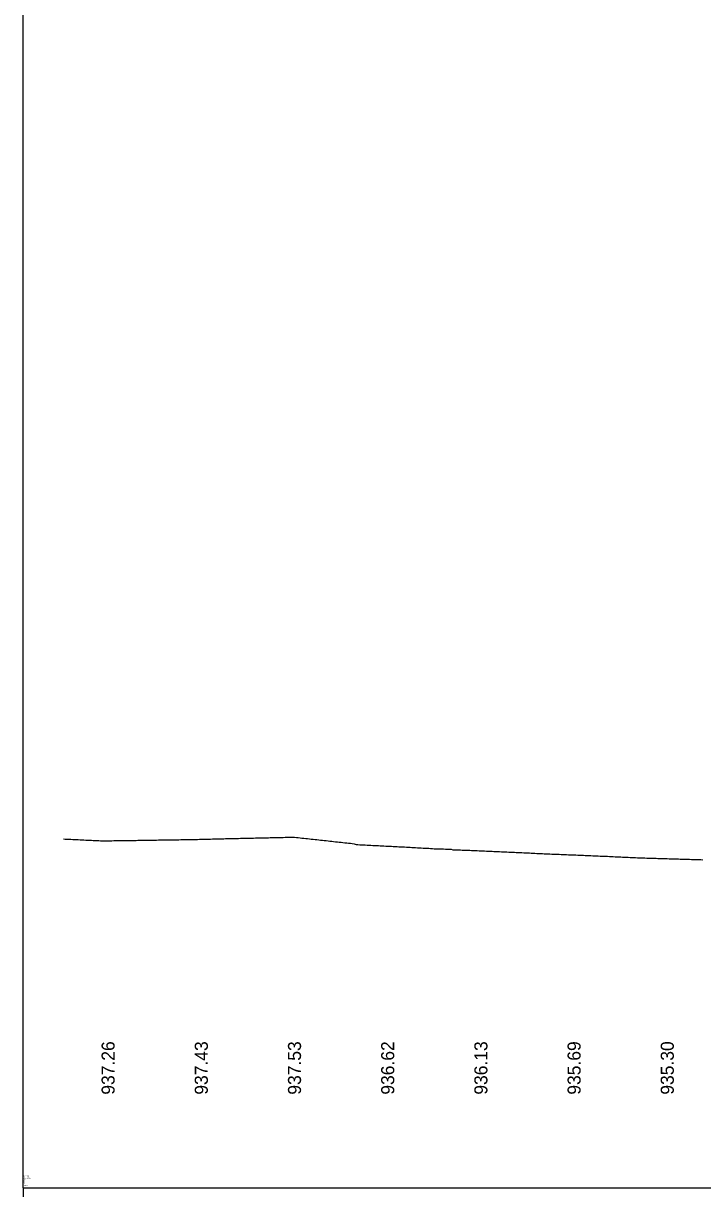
# Model space of a CAD drawing. Extents: x 1573485 to 1576468, y 1104256 to 1106756.
# Drawn here: x 1574956 to 1575320, y 1105506 to 1106131 of the extents above; entities that cross this region are included whole.
import ezdxf

# ---------------------------------------------------------------- set-up
doc = ezdxf.new("R2010")
doc.units = 0
for name, color, linetype in [('RD_DDB_Profile_EX', 7, 'Continuous'), ('RD_DDB_StripGrade', 7, 'Continuous'), ('RD_GPK_Profile_Cell', 7, 'Continuous')]:
    doc.layers.add(name, color=color, linetype=linetype)

msp = doc.modelspace()

# ---------------------------------------------------------------- linework, layer by layer
at = {"layer": 'RD_DDB_Profile_EX'}
for points in [[(1574977.5, 1105693.27), (1574978.5, 1105693.22), (1574979.5, 1105693.18), (1574980.5, 1105693.13), (1574981.5, 1105693.08), (1574982.5, 1105693.03), (1574983.5, 1105692.98), (1574984.5, 1105692.94), (1574985.5, 1105692.89), (1574986.5, 1105692.84), (1574987.5, 1105692.79), (1574988.5, 1105692.75), (1574989.5, 1105692.7), (1574990.5, 1105692.65), (1574991.5, 1105692.6), (1574992.5, 1105692.56), (1574993.5, 1105692.51), (1574994.5, 1105692.46), (1574995.5, 1105692.42), (1574996.5, 1105692.37), (1574997.5, 1105692.32), (1574998.5, 1105692.28), (1574999.5, 1105692.29), (1575000.5, 1105692.3), (1575001.5, 1105692.32), (1575002.5, 1105692.33), (1575003.5, 1105692.34), (1575004.5, 1105692.36), (1575005.5, 1105692.37), (1575006.5, 1105692.38), (1575007.5, 1105692.4), (1575008.5, 1105692.41), (1575009.5, 1105692.43), (1575010.5, 1105692.44), (1575011.5, 1105692.46), (1575012.5, 1105692.47), (1575013.5, 1105692.48), (1575014.5, 1105692.5), (1575015.5, 1105692.51), (1575016.5, 1105692.53), (1575017.5, 1105692.54), (1575018.5, 1105692.56), (1575019.5, 1105692.57), (1575020.5, 1105692.59), (1575021.5, 1105692.6), (1575022.5, 1105692.62), (1575023.5, 1105692.63), (1575024.5, 1105692.65), (1575025.5, 1105692.66), (1575026.5, 1105692.68), (1575027.5, 1105692.69), (1575028.5, 1105692.71), (1575029.5, 1105692.72), (1575030.5, 1105692.74), (1575031.5, 1105692.76), (1575032.5, 1105692.77), (1575033.5, 1105692.79), (1575034.5, 1105692.8), (1575035.5, 1105692.82), (1575036.5, 1105692.84), (1575037.5, 1105692.85), (1575038.5, 1105692.87), (1575039.5, 1105692.88), (1575040.5, 1105692.9), (1575041.5, 1105692.92), (1575042.5, 1105692.93), (1575043.5, 1105692.95), (1575044.5, 1105692.97), (1575045.5, 1105692.98), (1575046.5, 1105693), (1575047.5, 1105693.02), (1575048.5, 1105693.03), (1575049.5, 1105693.05), (1575050.5, 1105693.08), (1575051.5, 1105693.11), (1575052.5, 1105693.13), (1575053.5, 1105693.16), (1575054.5, 1105693.18), (1575055.5, 1105693.21), (1575056.5, 1105693.23), (1575057.5, 1105693.26), (1575058.5, 1105693.28), (1575059.5, 1105693.3), (1575060.5, 1105693.33), (1575061.5, 1105693.35), (1575062.5, 1105693.38), (1575063.5, 1105693.4), (1575064.5, 1105693.43), (1575065.5, 1105693.45), (1575066.5, 1105693.47), (1575067.5, 1105693.5), (1575068.5, 1105693.52), (1575069.5, 1105693.54), (1575070.5, 1105693.57), (1575071.5, 1105693.59), (1575072.5, 1105693.61), (1575073.5, 1105693.64), (1575074.5, 1105693.66), (1575075.5, 1105693.68), (1575076.5, 1105693.71), (1575077.5, 1105693.73)], [(1575077.5, 1105693.73), (1575078.5, 1105693.75), (1575079.5, 1105693.78), (1575080.5, 1105693.8), (1575081.5, 1105693.82), (1575082.5, 1105693.84), (1575083.5, 1105693.87), (1575084.5, 1105693.89), (1575085.5, 1105693.91), (1575086.5, 1105693.93), (1575087.5, 1105693.96), (1575088.5, 1105693.98), (1575089.5, 1105694), (1575090.5, 1105694.02), (1575091.5, 1105694.05), (1575092.5, 1105694.07), (1575093.5, 1105694.09), (1575094.5, 1105694.11), (1575095.5, 1105694.13), (1575096.5, 1105694.16), (1575097.5, 1105694.18), (1575098.5, 1105694.2), (1575099.5, 1105694.22), (1575100.5, 1105694.24), (1575101.5, 1105694.21), (1575102.5, 1105694.1), (1575103.5, 1105694), (1575104.5, 1105693.89), (1575105.5, 1105693.78), (1575106.5, 1105693.67), (1575107.5, 1105693.56), (1575108.5, 1105693.45), (1575109.5, 1105693.34), (1575110.5, 1105693.23), (1575111.5, 1105693.12), (1575112.5, 1105693.01), (1575113.5, 1105692.9), (1575114.5, 1105692.8), (1575115.5, 1105692.69), (1575116.5, 1105692.58), (1575117.5, 1105692.47), (1575118.5, 1105692.36), (1575119.5, 1105692.25), (1575120.5, 1105692.14), (1575121.5, 1105692.03), (1575122.5, 1105691.92), (1575123.5, 1105691.81), (1575124.5, 1105691.7), (1575125.5, 1105691.6), (1575126.5, 1105691.49), (1575127.5, 1105691.38), (1575128.5, 1105691.27), (1575129.5, 1105691.16), (1575130.5, 1105691.05), (1575131.5, 1105690.93), (1575132.5, 1105690.76), (1575133.5, 1105690.59), (1575134.5, 1105690.32), (1575135.5, 1105690.23), (1575136.5, 1105690.18), (1575137.5, 1105690.14), (1575138.5, 1105690.09), (1575139.5, 1105690.04), (1575140.5, 1105689.99), (1575141.5, 1105689.94), (1575142.5, 1105689.89), (1575143.5, 1105689.84), (1575144.5, 1105689.79), (1575145.5, 1105689.74), (1575146.5, 1105689.69), (1575147.5, 1105689.64), (1575148.5, 1105689.59), (1575149.5, 1105689.54), (1575150.5, 1105689.49), (1575151.5, 1105689.44), (1575152.5, 1105689.39), (1575153.5, 1105689.33), (1575154.5, 1105689.28), (1575155.5, 1105689.23), (1575156.5, 1105689.18), (1575157.5, 1105689.12), (1575158.5, 1105689.07), (1575159.5, 1105689.01), (1575160.5, 1105688.96), (1575161.5, 1105688.91), (1575162.5, 1105688.85), (1575163.5, 1105688.8), (1575164.5, 1105688.74), (1575165.5, 1105688.69), (1575166.5, 1105688.63), (1575167.5, 1105688.58), (1575168.5, 1105688.52), (1575169.5, 1105688.46), (1575170.5, 1105688.41), (1575171.5, 1105688.35), (1575172.5, 1105688.29), (1575173.5, 1105688.24), (1575174.5, 1105688.18), (1575175.5, 1105688.12), (1575176.5, 1105688.06), (1575177.5, 1105688.01)], [(1575177.5, 1105688.01), (1575178.5, 1105687.95), (1575179.5, 1105687.89), (1575180.5, 1105687.89), (1575181.5, 1105687.89), (1575182.5, 1105687.85), (1575183.5, 1105687.82), (1575184.5, 1105687.79), (1575185.5, 1105687.75), (1575186.5, 1105687.52), (1575187.5, 1105687.48), (1575188.5, 1105687.45), (1575189.5, 1105687.41), (1575190.5, 1105687.37), (1575191.5, 1105687.33), (1575192.5, 1105687.29), (1575193.5, 1105687.25), (1575194.5, 1105687.21), (1575195.5, 1105687.17), (1575196.5, 1105687.13), (1575197.5, 1105687.09), (1575198.5, 1105687.05), (1575199.5, 1105687), (1575200.5, 1105686.96), (1575201.5, 1105686.92), (1575202.5, 1105686.88), (1575203.5, 1105686.84), (1575204.5, 1105686.79), (1575205.5, 1105686.75), (1575206.5, 1105686.71), (1575207.5, 1105686.66), (1575208.5, 1105686.62), (1575209.5, 1105686.58), (1575210.5, 1105686.53), (1575211.5, 1105686.49), (1575212.5, 1105686.44), (1575213.5, 1105686.4), (1575214.5, 1105686.35), (1575215.5, 1105686.31), (1575216.5, 1105686.26), (1575217.5, 1105686.22), (1575218.5, 1105686.17), (1575219.5, 1105686.13), (1575220.5, 1105686.08), (1575221.5, 1105686.03), (1575222.5, 1105685.99), (1575223.5, 1105685.94), (1575224.5, 1105685.89), (1575225.5, 1105685.84), (1575226.5, 1105685.79), (1575227.5, 1105685.75), (1575228.5, 1105685.7), (1575229.5, 1105685.65), (1575230.5, 1105685.6), (1575231.5, 1105685.55), (1575232.5, 1105685.5), (1575233.5, 1105685.45), (1575234.5, 1105685.4), (1575235.5, 1105685.36), (1575236.5, 1105685.32), (1575237.5, 1105685.27), (1575238.5, 1105685.23), (1575239.5, 1105685.19), (1575240.5, 1105685.15), (1575241.5, 1105685.11), (1575242.5, 1105685.07), (1575243.5, 1105685.03), (1575244.5, 1105684.99), (1575245.5, 1105684.96), (1575246.5, 1105684.92), (1575247.5, 1105684.88), (1575248.5, 1105684.84), (1575249.5, 1105684.8), (1575250.5, 1105684.76), (1575251.5, 1105684.72), (1575252.5, 1105684.68), (1575253.5, 1105684.64), (1575254.5, 1105684.59), (1575255.5, 1105684.55), (1575256.5, 1105684.51), (1575257.5, 1105684.47), (1575258.5, 1105684.43), (1575259.5, 1105684.38), (1575260.5, 1105684.34), (1575261.5, 1105684.3), (1575262.5, 1105684.26), (1575263.5, 1105684.21), (1575264.5, 1105684.17), (1575265.5, 1105684.12), (1575266.5, 1105684.08), (1575267.5, 1105684.04), (1575268.5, 1105683.99), (1575269.5, 1105683.95), (1575270.5, 1105683.9), (1575271.5, 1105683.86), (1575272.5, 1105683.81), (1575273.5, 1105683.76), (1575274.5, 1105683.72), (1575275.5, 1105683.67), (1575276.5, 1105683.62), (1575277.5, 1105683.58)], [(1575277.5, 1105683.58), (1575278.5, 1105683.53), (1575279.5, 1105683.48), (1575280.5, 1105683.44), (1575281.5, 1105683.39), (1575282.5, 1105683.34), (1575283.5, 1105683.29), (1575284.5, 1105683.24), (1575285.5, 1105683.2), (1575286.5, 1105683.16), (1575287.5, 1105683.13), (1575288.5, 1105683.1), (1575289.5, 1105683.07), (1575290.5, 1105683.04), (1575291.5, 1105683.01), (1575292.5, 1105682.98), (1575293.5, 1105682.95), (1575294.5, 1105682.92), (1575295.5, 1105682.89), (1575296.5, 1105682.86), (1575297.5, 1105682.83), (1575298.5, 1105682.8), (1575299.5, 1105682.77), (1575300.5, 1105682.74), (1575301.5, 1105682.71), (1575302.5, 1105682.68), (1575303.5, 1105682.65), (1575304.5, 1105682.62), (1575305.5, 1105682.59), (1575306.5, 1105682.56), (1575307.5, 1105682.53), (1575308.5, 1105682.5), (1575309.5, 1105682.47), (1575310.5, 1105682.44), (1575311.5, 1105682.41), (1575312.5, 1105682.38), (1575313.5, 1105682.35), (1575314.5, 1105682.32), (1575315.5, 1105682.29), (1575316.5, 1105682.26), (1575317.5, 1105682.23), (1575318.5, 1105682.2), (1575319.5, 1105682.17), (1575320.5, 1105682.14)]]:
    msp.add_lwpolyline(points, dxfattribs=at)
at = {"layer": 'RD_GPK_Profile_Cell'}
for q in [(1574956, 1106756.08), (1576456, 1105506.08), (1574956, 1104256.08)]:
    msp.add_line((1574956, 1105506.08), q, dxfattribs=at)

# ---------------------------------------------------------------- texts
at = {"layer": 'RD_DDB_StripGrade'}
for s, p in [('937.26', (1575005, 1105556.08)), ('937.43', (1575055, 1105556.08)), ('937.53', (1575105, 1105556.08)), ('936.62', (1575155, 1105556.08)), ('936.13', (1575205, 1105556.08)), ('935.69', (1575255, 1105556.08)), ('935.30', (1575305, 1105556.08))]:
    msp.add_text(s, height=7, rotation=90, dxfattribs=at).set_placement(p)
at = {"layer": 'RD_GPK_Profile_Cell'}
for s, p in [('01', (1574956, 1105513.08)), ('S147_REL', (1574956, 1105512.08)), ('900', (1574956, 1105510.08)), ('50', (1574956, 1105509.08)), ('1200.000000', (1574956, 1105511.08)), ('10', (1574956, 1105508.08)), ('NOGAP', (1574956, 1105507.08))]:
    msp.add_text(s, height=0.5, dxfattribs=at).set_placement(p)

doc.saveas('drawing.dxf')
